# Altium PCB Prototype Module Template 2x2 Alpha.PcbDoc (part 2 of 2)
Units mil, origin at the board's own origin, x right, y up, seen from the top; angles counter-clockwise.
Board outline 1561.03 x 1620.2 mil, 6 copper layers (Component Side, Ground Plane (GND), Inner Layer 1, Inner Layer 2, Power Plane (VCC), Solder Side), stack 51.068 mil thick; 166 components, 80 nets, 785 pads, 445 vias.
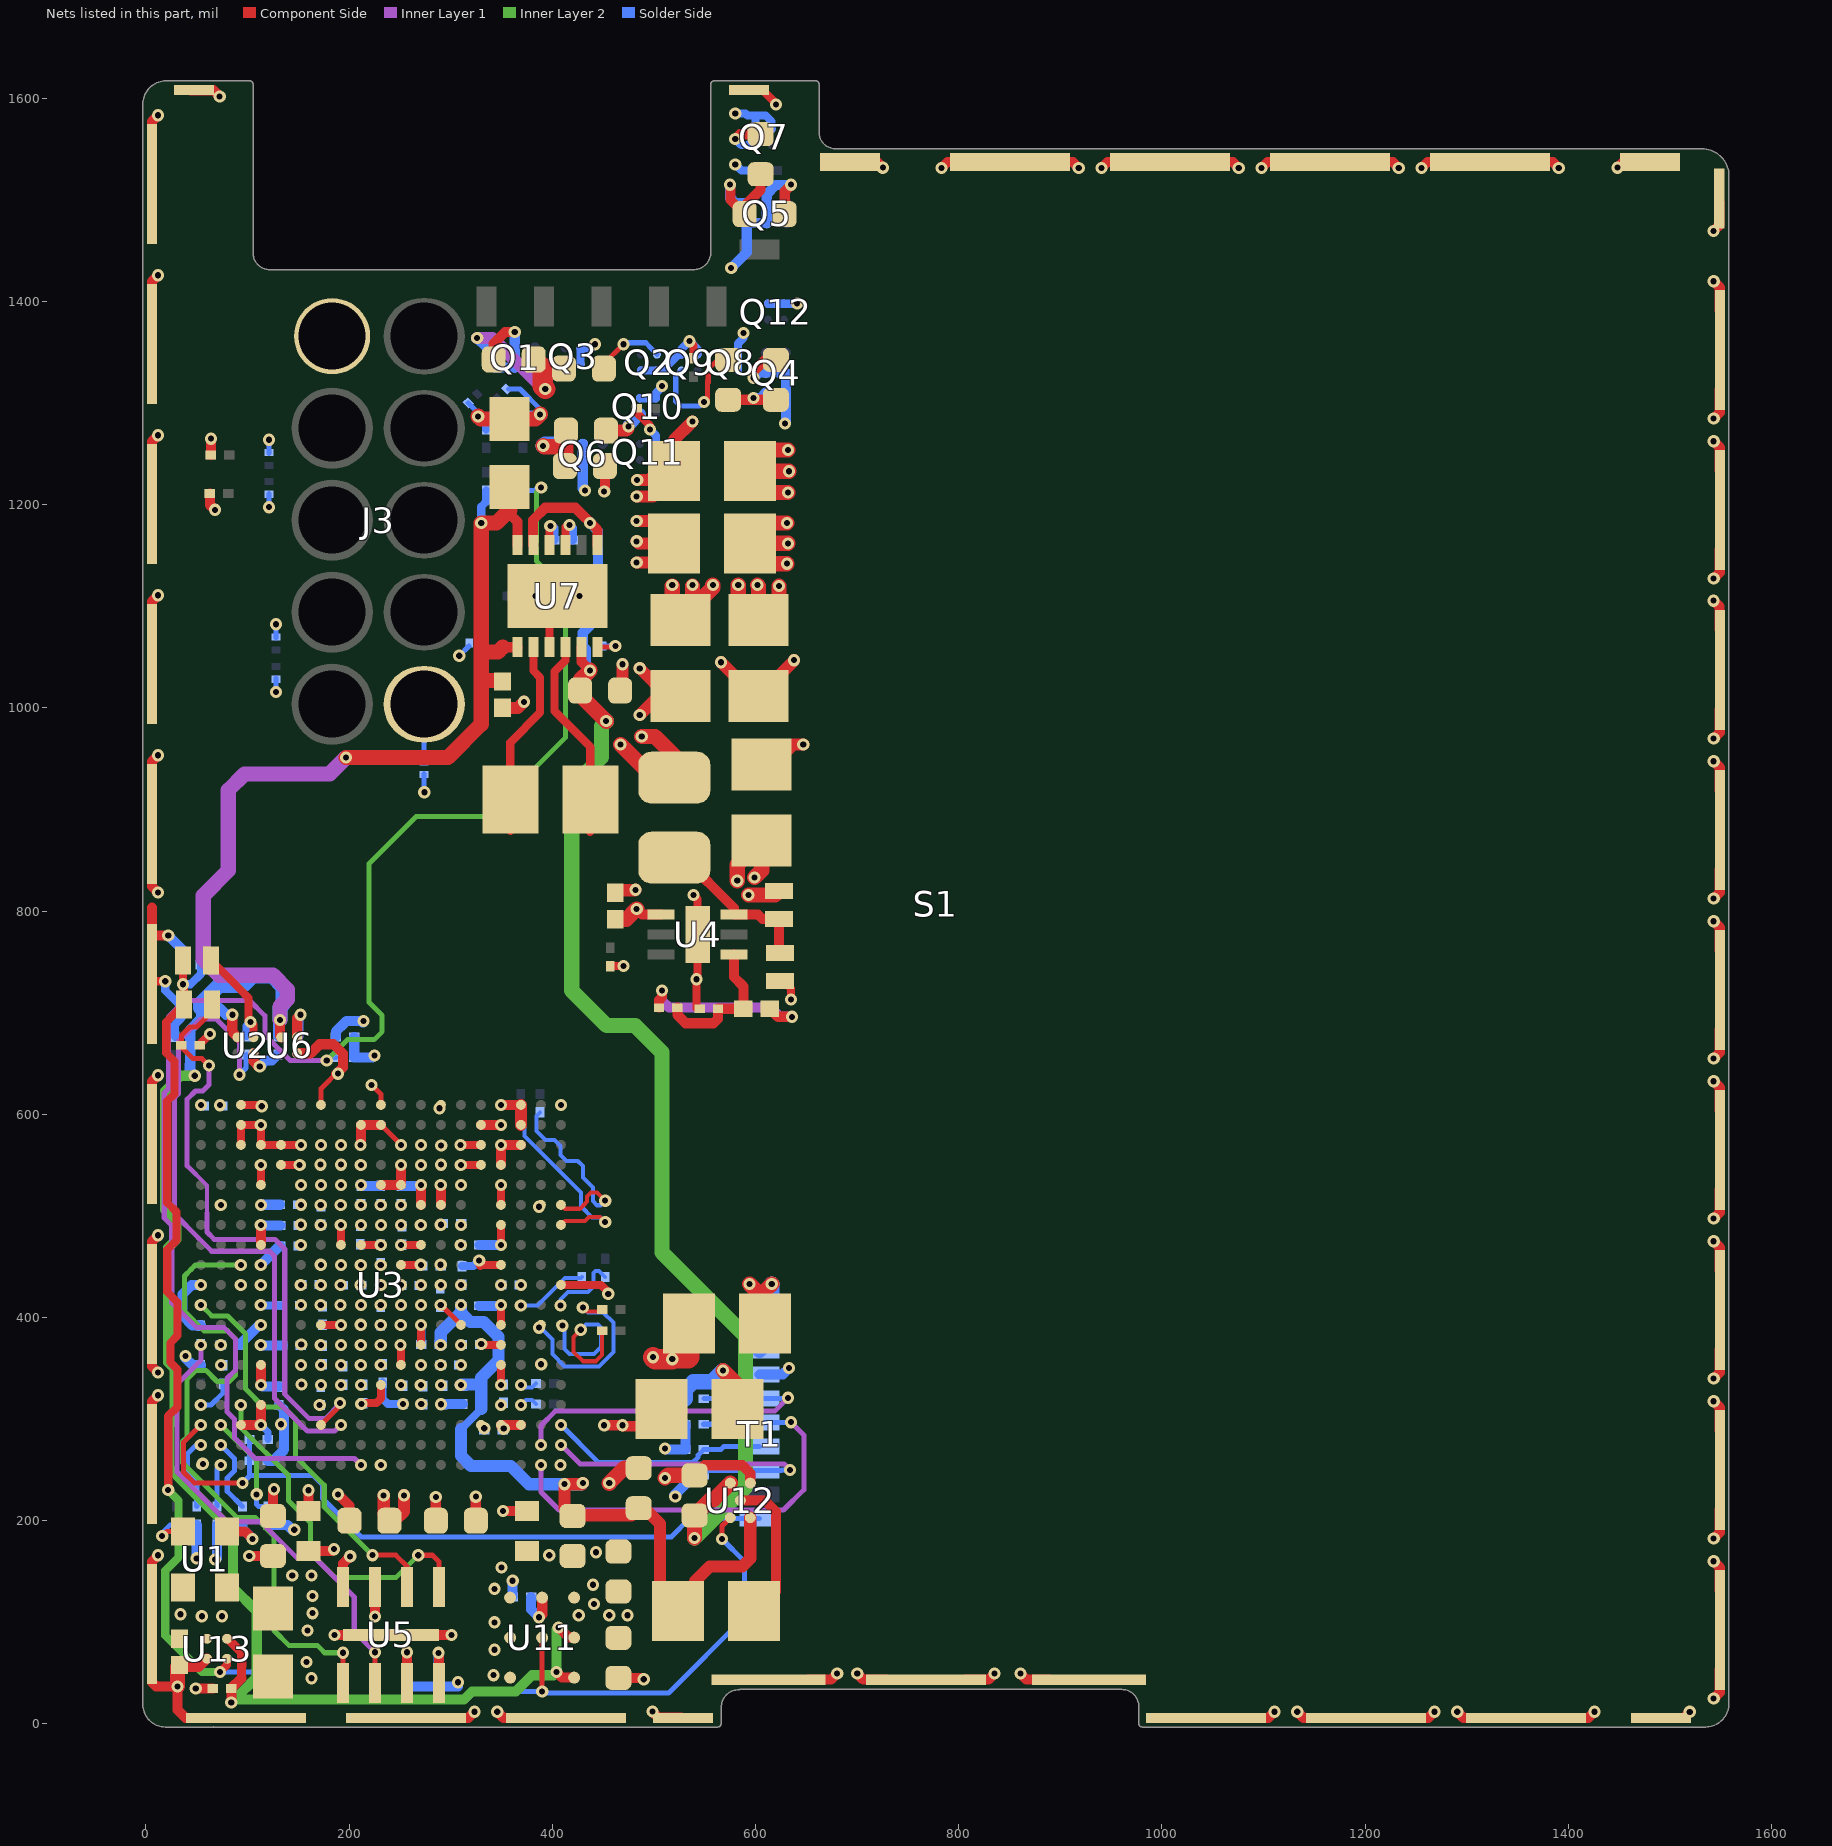
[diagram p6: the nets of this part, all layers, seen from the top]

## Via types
v1: diameter 12, hole 6, Component Side to Solder Side, tented both sides, 444 vias
v2: diameter 12, hole 6, Component Side to Solder Side, 1 vias

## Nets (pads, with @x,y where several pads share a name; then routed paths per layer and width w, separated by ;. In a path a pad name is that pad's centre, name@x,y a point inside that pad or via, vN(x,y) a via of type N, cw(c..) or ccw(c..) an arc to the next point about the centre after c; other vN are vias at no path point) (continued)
GND: C1.1 C2.1 C3.1 C4.1 C5.1 C6.1 C7.1 C8.1 C9.1 C11.1 C12.2 C13.2 C14.2 C15.2 C16.1 C17.2 C18.1 C19.1 C20.1 C21.1 C22.1 C23.1 C24.1 C25.1 C26.1 C27.1 C28.1 C29.1 C30.1 C31.1 C32.1 C33.1 C34.1 C35.1 C36.1 C37.1 C38.1 C39.1 C40.1 C41.1 C44.1 C49.1 C50.1 C51.1 C52.1 C53.1 C57.1 C58.1 C59.1 C60.1 C61.1 C62.1 C63.1 C64.1 C65.1 C66.1 C67.1 C68.1 C69.1 C70.1 C71.1 C72.1 C73.1 C77.1 C78.1 C81.1 C82.1 C94.1 C95.1 D2.1 J3.10 Q2.2 Q2.3 Q3.2 Q3.3 Q7.2 Q7.3 Q8.2 Q8.3 Q9.2 Q9.3 Q10.2 Q10.3 Q11.2 Q11.3 Q12.2 Q12.3 R1.2 R2.1 R5.2 R6.2 R9.2 R14.2 R15.2 R20.1 R21.2 R23.2 R24.2 R25.2 R30.2 R31.2 R32.2 R33.2 R41.1 R43.1 R45.1 R59.2 R60.2 R61.2 R62.2 S1.S T1.1 TVS1.2 TVS2.2 TVS3.2 TVS4.2 TVS5.2 TVS6.2 TVS7.2 TVS8.2 TVS9.2 U1.2 U2.B1 U3.A1 U3.A10 U3.A19 U3.C3 U3.C4 U3.C16 U3.C17 U3.D16 U3.E4 U3.E10 U3.E12 U3.E16 U3.F2 U3.F4 U3.F6 U3.F9 U3.F11 U3.F13 U3.F16 U3.F18 U3.G4 U3.G8 U3.G9 U3.G11 U3.G12 U3.G16 U3.H4 U3.H6 U3.H8 U3.H10 U3.H12 U3.H13 U3.H16 U3.J4 U3.J7 U3.J9 U3.J11 U3.J16 U3.K1 U3.K4 U3.K8 U3.K10 U3.K12 U3.K13 U3.K16 U3.K19 U3.L4 U3.L8 U3.L9 U3.L11 U3.L12 U3.L13 U3.L16 U3.M4 U3.M8 U3.M9 U3.M10 U3.M11 U3.M12 U3.M16 U3.N4 U3.N7 U3.N8 U3.N12 U3.N16 U3.P2 U3.P4 U3.P7 U3.P8 U3.P12 U3.P13 U3.P16 U3.P18 U3.R4 U3.R6 U3.R7 U3.R8 U3.R9 U3.R10 U3.R11 U3.R12 U3.R13 U3.R14 U3.R16 U3.T4 U3.T5 U3.T6 U3.T7 U3.T8 U3.T9 U3.T11 U3.T12 U3.T13 U3.T14 U3.T15 U3.T16 U3.U3 U3.U4 U3.U5 U3.U6 U3.U7 U3.U8 U3.U9 U3.U11 U3.U12 U3.U13 U3.U14 U3.U15 U3.U16 U3.U17 U3.V3 U3.V4 U3.V5 U3.V10 U3.V11 U3.V16 U3.V17 U3.W1 U3.W3 U3.W4 U3.W7 U3.W10 U3.W13 U3.W16 U3.W17 U3.W19 U4.7 U5.4 U5.9 U6.B1 U7.3 U7.9 U7.13 U11.C1 U11.C2 U11.C3 U12.A3 U13.B1 | length 6087
  Component Side w5: U3.W13@172.2,609.33 172.2,625.2 172.5,625.5 172.59,625.5 180.5,633.41 180.5,633.5 187,640 v1(189,640) ; v1(222,629) 231.26,619.74 U3.W10@231.26,609.33 ; U3.V10@231.26,589.65 v1(250.94,569.96) ; U3.J7@290.39,412.4 U3.H6@310,392.8
  Component Side w7: U3.F18@73.78,353.43 v1(74,353.2)
  Component Side w8: S1.S@8.56,731 v1(19,731) ; R41.1@53.06,668 53.06,669.06 v1(63,679) ; U3.U17@93.46,569.96 U3.V17@93.46,589.65 U3.V16@113.15,589.65 U3.U16@113.15,569.96 U3.U15@132.83,569.96 v1(152.52,569.96) ; U3.W17@93.46,609.33 U3.W16@113.15,609.33 114,608.48 v1(114,608) ; U3.R16@113.15,530.59 U3.T16@113.15,550.28 ; U3.T15@132.83,550.28 U3.T14@152.52,550.28 ; U3.H13@172.2,392.8 191.79,392.8 v1(191.87,392.72) ; v1(191.81,491.22) 191.89,491.15 U3.M12@191.89,471.54 ; U3.M11@211.57,471.54 231.07,471.54 v1(231.17,471.44) ; v1(212,314.94) 213.06,316 227,316 231.26,320.26 U3.E10@231.26,333.74 ; v1(250.69,373.03) 250.94,372.77 U3.F9@250.94,353.43 ; U3.L9@250.94,451.85 270.5,451.85 v1(270.55,451.9) ; v1(250.94,471.54) U3.M8@270.63,471.54 ; U3.G8@270.63,373.11 v1(270.63,392.8) ; v1(290.13,412.4) U3.J7@290.39,412.4 ; U3.T6@310,550.28 U3.T5@329.69,550.28 ; U3.U6@310,569.96 U3.U5@329.69,569.96 ; v1@328,453 v1(328,456) ; v1@329,451 329.85,451.85 U3.L4@349.37,451.85 ; v1(330,374) 330.89,373.11 U3.G4@349.37,373.11 ; v1(349.37,333.74) U3.F4@349.37,353.43 ; U3.H4@349.37,392.8 v1(349.37,412.48) ; v1(349.37,471.54) U3.N4@349.37,491.22 ; U3.P4@349.37,510.91 v1(349.37,530.59) ; U7.3@397.13,1059.8 397.13,1102.13 U7.13@405,1110 ; U3.K1@408.43,432.17 447.83,432.17 455,425 v1(455,423.33) ; U7.9@412.87,1160.2 413,1160.32 413,1178 415,1180 v1(417,1180) ; R9.2@457,745.94 469.94,745.94 v1(470,746) ; R61.2@482.94,1295 482.94,1290.93 492.21,1281.67 492.33,1281.67 496.02,1277.98 v1(496.02,1274.02) ; v1(535,1361) 539,1357 R62.2@539,1344.06 ; v1(539,816) 543,812 U4.7@543,777 543,735 v1@542,734 ; R14.2@541.94,704 541.94,733.94 v1@542,734 ; v1(542,733) v1@542,734 ; S1.S@595.47,1607.28 607.72,1607.28 620,1595 v1(620,1594) ; D2.1@624,731.22 627.78,731.22 635,724 v1(635,713)
  Component Side w10: 5.91,803.53 5.91,776.09 6,776 v1(22,776) ; S1.S@5.91,858.39 S1.S@5.91,885.83 ; S1.S@6,295 6,317.48 v1(12,323.48) ; S1.S@6,374.29 6,351.81 v1(12,345.81) ; S1.S@6,452.48 6,474.96 v1(12,480.96) ; S1.S@6,609.96 6,632.44 v1(12,638.44) ; S1.S@6,846.73 6,824.25 v1(12,818.25) ; S1.S@6,924.92 6,947.4 v1(12,953.4) ; S1.S@6,1082.4 6,1104.88 v1(12,1110.88) ; S1.S@6,1239.88 6,1262.36 v1(12,1268.36) ; S1.S@6,1397.36 6,1419.84 v1(12,1425.84) ; S1.S@6,1554.84 6,1577.32 v1(12,1583.32) ; v1(12,166) 5.91,159.91 S1.S@5.91,98.43 5.91,41.09 10,37 v1(31,37) 31,14 39,6 S1.S@45,6 ; C57.1@31,56.01 52.01,56.01 U13.B1@60.16,64.16 ; S1.S@44.09,1607.91 66.57,1607.91 v1(72.57,1601.91) ; v1(49,35) C94.1@65.94,35 ; R15.2@62.89,1211 62.89,1200.05 v1(67.94,1195) ; R31.2@63.89,1249 63.89,1264.94 v1(63.94,1265) ; U1.2@79.65,189.56 97.44,189.56 v1(105,182) ; U3.C17@93.46,294.37 U3.C16@113.15,294.37 U3.D16@113.15,314.06 ; v1(101.69,165.32) C60.1@125,165.32 ; U2.B1@105.87,660.13 105.87,652.13 111,647 v1(112,647) ; v1(113.15,333.74) U3.F16@113.15,353.43 ; U3.M16@113.15,471.54 U3.N16@113.15,491.22 ; U6.B1@148.87,660.13 162.13,660.13 171.04,669.04 184.63,669.04 194,659.67 194,646.41 v1@187.29,639.71 ; C16.1@160,170.32 v1@183.32,170.32 ; v1(185.6,87.6) U5.9@241.14,87.6 v1(300.6,87.6) ; v1(189,226) 200.32,214.68 C61.1@200.32,200 ; U5.4@193.9,134.84 193.9,157.9 v1(201,165) ; U3.U11@211.57,569.96 U3.V11@211.57,589.65 U3.V10@231.26,589.65 ; U3.R10@231.26,530.59 U3.R9@250.94,530.59 v1(250.94,550.28) ; v1(270.59,530.47) 270.63,530.43 U3.P8@270.63,510.91 ; v1(290.17,530.44) 290.32,530.29 U3.P7@290.32,510.91 ; S1.S@295,6 317.48,6 v1(323.48,12) ; C72.1@324.69,200 v1(324.69,223.68) ; U3.V5@329.69,589.65 v1(349.37,589.65) ; v1(345.81,12) 351.81,6 S1.S@374.29,6 ; U3.T4@349.37,550.28 v1(349.37,569.96) U3.U3@369.06,569.96 ; v1(349.37,609.33) U3.W3@369.06,609.33 ; v1(352.2,290.6) 349.37,293.43 U3.C4@349.37,294.37 U3.C3@369.06,294.37 ; U3.F2@388.17,354 U3.F2@388.74,353.43 ; C41.1@465,45.32 488.69,45.32 v1(490,44) ; v1(498.44,12.09) 504.44,6.09 S1.S@526.92,6.09 ; C81.1@540,244.68 549.86,254.55 587.06,254.55 594.84,246.77 U12.A3@594.84,237.05 ; S1.S@651.85,43.6 674.33,43.6 v1(680.33,49.6) ; S1.S@696.78,1537.76 719.26,1537.76 v1(725.26,1531.76) ; v1(700.14,49.6) 706.14,43.6 S1.S@728.62,43.6 ; v1(783.02,1531.31) 789.02,1537.31 S1.S@811.5,1537.31 ; S1.S@806.81,43.6 829.29,43.6 v1(835.29,49.6) ; v1(860.65,49.6) 866.65,43.6 S1.S@889.13,43.6 ; S1.S@889.69,1537.31 912.17,1537.31 v1(918.17,1531.31) ; v1(940.5,1531.31) 946.5,1537.31 S1.S@968.98,1537.31 ; S1.S@1047.17,1537.31 1069.65,1537.31 v1(1075.65,1531.31) ; S1.S@1082.4,6 1104.88,6 v1(1110.88,12) ; v1(1097.98,1531.31) 1103.98,1537.31 S1.S@1126.46,1537.31 ; v1(1133.21,12) 1139.21,6 S1.S@1161.69,6 ; S1.S@1204.65,1537.31 1227.13,1537.31 v1(1233.13,1531.31) ; S1.S@1239.88,6 1262.36,6 v1(1268.36,12) ; v1(1255.46,1531.31) 1261.46,1537.31 S1.S@1283.94,1537.31 ; v1(1290.69,12) 1296.69,6 S1.S@1319.17,6 ; S1.S@1362.13,1537.31 1384.61,1537.31 v1(1390.61,1531.31) ; S1.S@1397.36,6 1419.84,6 v1(1425.84,12) ; v1(1448.36,1531.76) 1454.36,1537.76 S1.S@1476.84,1537.76 ; S1.S@1491.02,5.91 1513.5,5.91 v1(1519.5,11.91) ; v1(1542.91,1105.57) 1548.91,1099.57 S1.S@1548.91,1077.09 ; v1(1542.91,1469.43) 1548.91,1475.43 S1.S@1548.91,1497.91 ; v1(1543.04,24.95) 1549.04,30.95 S1.S@1549.04,53.43 ; v1(1543.04,160.09) 1549.04,154.09 S1.S@1549.04,131.61 ; v1(1543.04,182.43) 1549.04,188.43 S1.S@1549.04,210.91 ; v1(1543.04,317.57) 1549.04,311.57 S1.S@1549.04,289.09 ; v1(1543.04,339.91) 1549.04,345.91 S1.S@1549.04,368.39 ; v1(1543.04,475.06) 1549.04,469.06 S1.S@1549.04,446.57 ; v1(1543.04,497.39) 1549.04,503.39 S1.S@1549.04,525.87 ; v1(1543.04,632.54) 1549.04,626.54 S1.S@1549.04,604.06 ; v1(1543.04,654.87) 1549.04,660.87 S1.S@1549.04,683.35 ; v1(1543.04,790.02) 1549.04,784.02 S1.S@1549.04,761.54 ; v1(1543.04,812.35) 1549.04,818.35 S1.S@1549.04,840.83 ; v1(1543.04,947.5) 1549.04,941.5 S1.S@1549.04,919.02 ; v1(1543.04,969.83) 1549.04,975.83 S1.S@1549.04,998.31 ; v1(1543.04,1127.31) 1549.04,1133.31 S1.S@1549.04,1155.79 ; v1(1543.04,1262.46) 1549.04,1256.46 S1.S@1549.04,1233.98 ; v1(1543.04,1284.79) 1549.04,1290.79 S1.S@1549.04,1313.27 ; v1(1543.04,1419.94) 1549.04,1413.94 S1.S@1549.04,1391.46
  Component Side w12: C77.1@351,1000.01 366.01,1000.01 v1(372,1006) ; U3.V3@369.06,589.65 U3.W3@369.06,609.33 ; C9.1@462,817.99 464.51,820.5 481.5,820.5 v1(482,821) ; C50.1@466.69,1017 469,1019.32 v1(469,1043) ; v1(483,1143) 500.6,1143 C8.1@519.6,1162 ; v1(483,1164) 485,1162 C8.1@519.6,1162 ; v1(483,1184) 497.6,1184 C8.1@519.6,1162 ; v1(483,1208) 499,1208 519.6,1228.6 C11.1@519.6,1233 ; v1(483.52,1224.48) 495.48,1224.48 504,1233 C11.1@519.6,1233 ; v1(486,993) 504.6,1011.6 C31.1@513.4,1011.6 ; v1(486,1039) C31.1@513.4,1011.6 ; C31.1@526,1011.6 C31.1@513.4,1011.6 ; v1(538,1282) 519.6,1263.6 C11.1@519.6,1233 ; v1(566,1045) 599.4,1011.6 C53.1@603,1011.6 638,1046.6 v1(638,1047) ; C49.1@606,944.4 617.4,944.4 637,964 v1(647,964)
  Component Side w15: v1(31,37) 31,56.01 C57.1@33,58.01 ; v1(327,1287) 329.54,1284.46 C52.1@358,1284.46 383.46,1284.46 v1(388,1289) ; v1(456,237) 470.69,251.68 C82.1@485,251.68 ; v1(511,242) 514,245 514.32,244.68 C81.1@540,244.68 ; v1(568,348) 582.4,333.6 C38.1@582.4,310 C38.1@582.4,330.4 ; v1(594,433) C78.1@609.4,417.6 ; C78.1@609.4,394 C78.1@609.4,417.6 ; v1(616,433) 609.4,426.4 C78.1@609.4,417.6
  Solder Side w5: v1(121,1197.61) TVS8.2@121,1211.21 ; TVS7.2@121,1250.39 v1(121,1264) ; v1(128,1015.61) TVS6.2@128,1029.21 ; TVS5.2@128,1068.79 v1(128,1082.39) ; v1@273.86,917 TVS9.2@273.86,935.35 ; v1(308.38,1051.38) TVS2.2@318,1061 ; TVS4.2@317.19,1300.19 329,1288.37 v1@329,1287 ; TVS3.2@356.81,1313.81 368.19,1313.81 388,1294 v1(388,1289) ; TVS1.2@368.39,1110 v1(383.35,1110)
  Solder Side w7: v1(113.07,294.29) 120.06,287.31 C14.2@120.06,280
  Solder Side w8: v1(19,731) 19,721.94 C32.1@35.94,705 35,704.05 35,695 28.54,688.54 R59.2@28.54,676.38 ; v1(113.07,412.4) 113.47,412 C73.1@133.94,412 ; C5.1@173.69,392.71 v1(191.87,392.72) ; C1.1@211,471.94 211.5,471.44 v1(231.17,471.44) ; C36.1@233,335.94 233,320 238.06,314.94 v1(253,314.94) ; v1(270.63,392.8) 271.12,392.31 C64.1@271.12,373.52 ; C6.1@311.17,450.57 322.57,450.57 v1(328,456) ; v1@328,1288 v1(327,1287) 329,1287 335,1281 R5.2@335,1274.06 ; R6.2@371,1274.06 371,1281 379,1289 v1(388,1289) ; v1(417,1180) 420.06,1176.94 R43.1@420.06,1165 ; Q3.2@427.87,1338.13 Q3.3@427.87,1353.87 437.87,1353.87 v1(442,1358) ; Q10.3@486.13,1304.87 Q10.2@501.87,1304.87 501.87,1309.87 509,1317 v1(508,1317) ; Q2.2@487.13,1332.13 Q2.3@502.87,1332.13 508.69,1332.13 524.44,1347.87 Q9.3@527.13,1347.87 527.13,1353.13 v1(535,1361) 542.87,1353.13 Q9.2@542.87,1347.87 ; v1(496.02,1274.02) 501.87,1268.13 Q11.3@501.87,1259.87 Q11.2@501.87,1244.13 ; v1(580,1535) 586,1529 R60.2@602.94,1529 ; v1(580,1585) 590,1585 592,1583 602,1583 ; Q8.2@582.87,1332.13 Q8.3@582.87,1347.87 582.87,1358.87 588,1364 v1(588,1369) ; Q7.3@600.13,1569.87 600.13,1581.13 602,1583 ; Q12.3@612.13,1397.87 Q12.2@627.87,1397.87 640.87,1397.87 v1(641,1398) ; Q7.2@615.87,1569.87 615.87,1577.13 610,1583 602,1583
  Solder Side w10: v1(22,776) 35.94,762.06 R1.2@35.94,747 ; v1(50,163) R24.2@50,195.94 ; R20.1@54,392.06 45.94,392.06 36,402 36,423 45.09,432.09 v1(54.02,432.09) ; v1(68,162) 69,162 70,163 R25.2@70,195.94 ; R21.2@91.81,373.03 111.5,392.72 v1(113.07,392.72) ; R23.2@95,195.94 95,192 v1(105,182) ; v1(112,647) 118,653 124.06,653 C39.1@130,658.94 ; v1(113.07,373.03) 113.58,372.52 C18.1@134.12,372.52 ; v1(113.07,451.77) 131.82,470.52 C69.1@132.12,470.52 ; v1(113.07,491.14) 113.69,490.52 C28.1@132.12,490.52 ; v1(113.15,333.74) 114.83,332.06 C34.1@131,332.06 ; v1(113.15,510.91) 113.24,511 C71.1@131.94,511 ; C3.1@205.06,676 R2.1@205.06,656 223,656 v1(225,658) ; v1(211.57,530.59) 212.59,529.57 C30.1@231.17,529.57 ; C33.1@251.17,529.57 269.7,529.57 v1(270.59,530.47) ; C13.2@257,36.94 C12.2@288,36.94 306.94,36.94 307,37 v1(307,41) ; v1(290.32,314.63) 290.63,314.94 C63.1@312,314.94 ; C65.1@328.23,411.52 348.41,411.52 v1(349.37,412.48) ; C24.1@328.23,471.52 v1(349.37,471.54) ; R45.1@360.94,125 v1(360.94,140.94)
  Solder Side w15: R32.2@530.94,320 530.94,329.02 538.76,336.83 556.83,336.83 v1(568,348) ; T1.1@604,367.68 604,393 616,405 v1(616,433)
  other v1: 163,45 342,48 158,61 343,73 343,100 343,133 350,154 397,166 443,169 185,172 231.18,254.92 408,255 56,256 171,314 271,315 191.89,333.74 172.2,353.43 211.5,353.35 310,353.35 389,354 191.89,373.11 211.5,373.03 231.09,392.63 211.54,412.44 250.91,412.44 113.07,432.09 172.13,431.97 191.74,432.09 231.18,432.03 270.59,432.04 349.37,432.17 172.13,451.91 191.93,451.77 211.5,451.84 270.55,490.98 290.24,491.3 387,509 73.7,510.83 172.09,510.86 191.71,510.83 309.99,530.44 152.52,530.59 172.2,530.59 191.89,530.59 113.07,550.2 151.34,550.2 171.88,550.44 192.06,550.44 211.5,550.2 270.59,550.24 290.48,550.44 309.92,550.27 290.59,569.44 172.2,569.96 192.04,569.88 211.09,569.94 270.63,569.96 309.59,569.94 113.07,589.46 289,606 54.09,609.33 408.43,609.33 274,917 426.65,1110
INITN: R26.1 U3.C18 | length 104.7
  Inner Layer 2 w5: v1(73.7,294.29) 109,258.99 v1(109,226)
  Solder Side w5: v1(109,226) 109,216 110.94,214.06 R26.1@120,214.06
NetC10_1: C10.1 R13.2 R14.1 U4.1 | length 144.3
  Component Side w10: R13.2@523.06,705 523.06,697.94 531.33,689.67 558.67,689.67 563.06,694.06 R14.1@563.06,704 C10.1@588.01,704 588.01,725.99 578.83,735.17 U4.1@578.83,757.31
NetD1_1: D1.1 D2.2 L2.2 U4.3 | length 165.7
  Component Side w10: L2.2@520,852.63 529.37,852.63 578.83,803.17 U4.3@578.83,796.68 602.32,796.68 606.78,792.22 D1.1@623,792.22 623,759.78 D2.2@624,758.78
NetL1_1: L1.1 U12.B2 | length 154.2
  Component Side w10: U12.B2@585,220 609,220 620,209 620,130.6 L1.1@594.4,105
NetL6_1: L6.1 U7.2 | length 202.2
  Component Side w8: L6.1@359,879 358.63,879.37 L6.1@358.63,910 358.63,966 388,995.37 388,1030 381.38,1036.62 ; 381.38,1043 381.38,1036.62 ; U7.2@381.38,1059.8 381.38,1036.62
NetL6_2: L6.2 U7.4 | length 201.1
  Component Side w8: U7.4@412.87,1059.8 412.87,1046.87 402,1036 402,997 437.37,961.63 L6.2@437.37,910 437.37,878.37 L6.2@437,878
NetQ1_1: Q1.1 R11.2 R12.1 | length 163.1
  Component Side w20: R11.2@381.69,1343 R11.2@390.69,1334 ; v1(393,1314) 390.69,1316.31 R11.2@390.69,1334 ; R12.1@411.32,1334 R11.2@390.69,1334
  Inner Layer 1 w12: v1(326,1364) 341,1364 391,1314 v1(393,1314)
  Solder Side w10: v1(326,1364) 335.16,1354.84 Q1.1@343.32,1354.84
NetQ2_4: Q2.4 R12.2 | length 99.2
  Component Side w5: R12.2@450.69,1334 450.69,1338.69 v1(470,1358)
  Solder Side w5: v1(470,1358) v1@471.41,1359.41 ; 497.66,1353.66 491.9,1359.41 ; Q2.4@502.87,1347.87 502.87,1348.44 491.9,1359.41 ; v1@471.41,1359.41 491.9,1359.41 ; v1@471.41,1359.41 484,1359.41 491.9,1359.41
NetQ4_1: Q4.1 R44.2 R58.1 | length 63.7
  Component Side w10: R58.1@573,1303.32 v1@596.32,1303.32 ; v1(598,1305) v1@596.32,1303.32 ; R44.2@620,1303.31 v1@596.32,1303.31
  Solder Side w10: v1(598,1305) 604.84,1305 Q4.1@610.16,1310.32
NetQ5_1: Q5.1 R16.2 R18.1 | length 112.2
  Component Side w10: v1(575,1515) 575.31,1514.69 575.31,1500 R16.2@589.31,1486 589.31,1494.31 605,1510 R18.1@605,1525.32
  Solder Side w10: v1(575,1515) 575,1502 580.16,1496.84 Q5.1@591.32,1496.84
NetQ6_1: Q6.1 R17.2 R19.1 | length 78.2
  Component Side w15: v1(391,1258) 392,1257 413.32,1257 ; R17.2@412.31,1238 413.32,1239 413.32,1257 ; R19.1@413.32,1273 413.32,1257
  Solder Side w15: v1(391,1258) 392.84,1259.84 Q6.1@410.32,1259.84
NetQ7_4: Q7.4 R18.2 | length 49.5
  Component Side w10: v1(580,1560) 584.69,1564.69 R18.2@605,1564.69
  Solder Side w8: v1(580,1560) 585.87,1554.13 Q7.4@600.13,1554.13
NetQ9_4: Q9.4 R58.2 | length 126.7
  Component Side w5: v1(549.2,1301.16) 549,1300.96 549,1300 552.7,1303.7 552.7,1322.28 553.42,1323 ; 553.42,1320.42 553.42,1323 ; R58.2@573,1342.69 562.69,1342.69 553.42,1333.42 553.42,1323
  Solder Side w5: Q9.4@527.13,1332.13 521.5,1326.5 521.5,1301.5 526,1297 545.04,1297 v1(549.2,1301.16)
NetQ10_4: Q10.4 R19.2 | length 41.9
  Component Side w12: R19.2@452.69,1273 473,1273 475,1275 v1(475,1277)
  Solder Side w12: v1(475,1277) 475,1278 Q10.4@486.13,1289.13
NetR21_1: R21.1 U3.G18
  other v1: 73.7,373.03
NetR23_1: R23.1 U3.B18 | length 78.5
  Solder Side w5: v1(73.7,274.61) 87.2,261.11 87.2,249.16 ; 85.44,247.4 87.2,249.16 ; R23.1@94.5,214.55 R23.1@95,214.06 80,229.06 80,241.96 87.2,249.16
NetR24_1: R24.1 U3.B19 | length 72.3
  Solder Side w5: R24.1@50,214.06 50,237 41,246 41,266 49.61,274.61 v1(54.02,274.61)
NetR25_1: R25.1 U3.A18 | length 42.4
  Solder Side w5: R25.1@70,214.06 70,251.22 v1(73.7,254.92)
NetR30_1: R30.1 U3.D19 | length 35.9
  Solder Side w5: v1(54.02,313.98) 63.98,313.98 76,326 R30.1@76,334.94
NetR33_1: R33.1 U3.W18
  other v1: 73,609
NetR35_1: R35.1 U6.B2 | length 42.4
  Component Side w10: U6.B2@148.87,675.87 148.87,694.87 v1(152,698)
  Solder Side w10: R35.1@150,677.06 v1@150,696
NetR39_2: R39.2 U7.6 | length 32.3
  Component Side w5: U7.6@444.5,1059.67 U7.6@444.37,1059.8 460.8,1059.8 v1(462,1061)
  Solder Side w5: R39.2@448.06,1061 v1(462,1061)
NetR43_2: R43.2 U7.10 | length 38.8
  Component Side w8: U7.10@397.13,1160.2 397.13,1176.13 400,1179 v1(398,1179)
  Solder Side w8: v1(398,1179) 400,1179 401.94,1177.06 R43.2@401.94,1165
NetR45_2: R45.2 U11.B1 | length 43.9
  Component Side w10: v1(387,105) 390,108 U11.B1@390,124.37
  Solder Side w10: R45.2@379.06,125 379.06,112.94 v1(387,105)
NetR52_1: R52.1 U1.3 | length 44.6
  Component Side w5: v1(16,185) 18.56,187.56 20.56,189.56 U1.3@36.35,189.56
  Solder Side w5: v1@16,187.12 v1(16,185) 16,188 23.94,195.94 R52.1@30,195.94
POWER_EN: D3.2 D4.2 R1.1 U11.B2 U12.C1 U13.B2 | length 1548.5
  Component Side w5: v1(390,32) U11.B2@390,85 ; v1(567,182) 567,194.8 U12.C1@575.16,202.95
  Component Side w8: v1(21.91,230.17) 21.91,302.91 31,312 31,348.79 24,355.79 24,375.21 31,382.21 31,415 21,425 21,467 30,476 30,504 21,513 21,613 28,620 28,652.21 20,660.21 20,690.78 D4.2@37.22,708 37.22,727.22 v1(36.42,728.02) D3.2@36.42,751.61 ; v1(73,51) 79.84,57.84 U13.B2@79.84,64.16
  Inner Layer 2 w8: v1(21.91,230.17) 32,220.08 32,163.79 21.21,153 21,153 19,151 19,87 55,51 v1(73,51)
  Solder Side w5: v1(73,51) 109,51 136.56,23.44 315.44,23.44 324,32 v1(390,32) ; v1@391.5,30.5 514.5,30.5 589,105 589,160 v1(567,182)
  Solder Side w8: v1(36.42,728.02) 44,728.02 54.06,738.08 R1.1@54.06,747
POWER_HOLD: D4.1 R41.2 U3.C13 | length 605.2
  Component Side w5: v1(62.02,648.02) 55.04,655 46,655 34.94,666.05 R41.2@34.94,668 34.94,677.94 43,686 50,686 64.78,700.78 D4.1@64.78,708 ; U3.C13@172.2,294.37 191,313.17 v1(191,316)
  Inner Layer 1 w4: 48.92,541.08 60,530 60,503
  Inner Layer 1 w5: 48.92,541.08 40.59,549.41 40.59,614.92 48.67,623 56,623 62,629 v1(62.02,648.02) ; 60,503 60,484.14 67.14,477 127,477 136.65,467.35 136.65,324.58 160.73,300.5 171,300.5 176.59,300.5 191,314.91 v1(191,316)
PROGRAM_N: C14.1 R22.2 T1.7 U3.C19 | length 745.5
  Component Side w5: U3.C19@54.09,294.37 v1(54.02,294.29) 37,277.28 37,248 48,237 82,237 ; v1@91,237 82,237 ; v1(95,237) 82,237
  Solder Side w5: v1(95,237) 101.94,243.94 R22.2@101.94,259 C14.1@101.94,280 ; 102.39,244.5 125,244.5 ; 137.5,244.5 125,244.5 ; 165.59,243.5 170.09,239 ; 580,202.32 T1.7@604,202.32 ; T1.7@593.74,202.32 535.32,202.32 517,184 211.91,184 174,221.91 174,235.09 170.09,239 ; 125,244.5 164.59,244.5 170.09,239
RX_CLK_N: C90.2 U3.J1 | length 71.9
  Solder Side w4: v1(408,412) 408,417.66 415.34,425 435,425 440.33,430.33 440.33,444 442.27,445.94 446.01,445.94 C90.2@452,439.94
RX_CLK_P: C89.2 U3.J3 | length 71.6
  Solder Side w4: v1(369,412) 385.37,412 412.37,439 428.05,439 C89.2@429,439.94
RX_N: C88.2 U3.P1 | length 203.6
  Component Side w4: U3.P1@408.43,510.91 412.27,507.06 427,507.06 430.94,511 431,511 434,514 434,519 438,523 444,523 447,520 v1(452,515)
  Solder Side w4: 384.5,596.44 384.5,590 ; C88.2@388,601.94 384.5,598.44 384.5,590 ; v1(452,515) 447.5,510.5 444,510.5 440,514.5 440,528 430,538 430,549 425,554 414,554 408,560 408,569 402.31,574.69 393.31,574.69 384.5,583.5 384.5,590
RX_P: C87.2 U3.N1 | length 203.6
  Component Side w4: U3.N1@408.43,491.22 412.27,495.06 431.97,495.06 435.91,499 447,499 v1(452,494)
  Solder Side w4: C87.2@369,601.94 372.5,598.44 372.5,589 ; 372.5,596.44 372.5,589 ; v1(452,494) 447.5,498.5 439.03,498.5 428,509.53 428,523 372.5,578.5 372.5,587.5 372.5,589
SPI_FLASH_CLK: R20.2 U3.G19 U5.6 | length 459.3
  Component Side w5: U5.6@225.39,40.35 v1(225.39,70.61)
  Inner Layer 1 w5: 48.16,352.06 54.02,357.92 v1(54.02,373.03) ; 52.5,356.41 46,349.91 30.52,334.42 30.52,323.71 30.52,248.25 79.77,199 113,199 149,163 167,163 205,125 205,91 v1(225.39,70.61)
SPI_FLASH_CS_N: U3.D17 U5.1 | length 347.3
  Component Side w5: v1(268,166) 282,166 288.39,159.61 U5.1@288.39,134.84
  Inner Layer 2 w5: v1(93.39,313.98) 93.39,291.61 140.27,244.73 140.27,219.73 162,198 162,168 186,144 246,144 v1(268,166)
SPI_FLASH_MISO: U3.J19 U5.2 | length 410.1
  Component Side w5: v1(222.89,166.11) 246,166.11 256.89,155.22 U5.2@256.89,134.84
  Inner Layer 2 w5: v1(54.02,412.4) 64.71,401.71 80.29,401.71 98,384 98,329.8 115.8,312 135.09,312 147,300.09 147,263.5 ; 147,278 147,263.5 ; v1(222.89,166.11) 175.5,213.5 175.5,231.59 175.5,235 147,263.5
SPI_FLASH_MOSI: U3.L17 U5.5 | length 654
  Component Side w5: U5.5@193.9,40.35 v1(193.9,70.1)
  Inner Layer 2 w5: v1(93.39,451.77) 48.86,451.77 44.59,447.5 44.5,447.5 38,441 38,406 57,387 80,387 88,379 88,343 82,337 70,337 59,348 49.26,348 40.59,339.33 40.59,329.59 40.52,329.52 40.52,288.62 40.59,288.54 40.59,282.59 36,278 36,257 42.5,250.5 42.5,250.41 50.41,242.5 50.5,242.5 90,203 108,203 126,185 126,92 141,77 169,77 175,71 175.9,70.1 v1(193.9,70.1)
TCK: R32.1 T1.3 U3.B2 | length 374.1
  Inner Layer 1 w5: v1(388.74,274.68) 388.74,293.78 402.83,307.87 618.87,307.87 v1(632,321)
  Solder Side w5: R32.1@549.49,320.43 T1.3@593.74,320.43 ; 576,320.43 T1.3@604,320.43 631.43,320.43 v1(632,321)
TDI: R28.2 T1.5 U3.C1 | length 233.2
  Solder Side w5: v1(408.43,294.37) 445.3,257.5 538.5,257.5 543.56,262.56 543.56,264.51 R28.2@549.06,270 565.81,270 569,273.19 579,273.19 ; T1.5@593.74,273.19 579,273.19 ; T1.5@604,273.19 579,273.19
TDO: R29.2 T1.6 U3.B1 | length 323
  Inner Layer 1 w5: v1(408.43,274.68) 427.11,256 628,256 v1(634,250)
  Solder Side w5: R29.2@549.06,245 553.62,249.57 625.57,249.57 625.57,249.43 626.13,250 v1(634,250)
TMS: R27.2 T1.4 U3.A2 | length 475.2
  Inner Layer 1 w5: v1(388.74,255) 388.74,228.26 406.5,210.5 511,210.5 ; 526.59,210.5 511,210.5 ; v1(635,297) 647.5,284.5 647.5,230.5 627.5,210.5 511,210.5
  Solder Side w5: R27.2@549.06,295 571.19,295 573,296.81 T1.4@604,296.81 634.81,296.81 v1(635,297)
TX_CLK_N: C86.2 U3.H2 | length 191.6
  Component Side w4: v1(430,410) 434,406 443,406 ; C86.2@444.95,406 443,406 ; C86.2@448.94,408 446.95,406 443,406
  Solder Side w4: v1(387,390) 388.38,390 400,378.38 400,364 412,352 446,352 460,366 460,395 450,405 436,405 435,405 v1(430,410)
TX_CLK_P: C85.2 U3.H1 | length 190.3
  Component Side w4: v1(428,388) 421,381 421,366 430,357 443,357 448.94,362.94 C85.2@448.94,387
  Solder Side w4: v1(410,392) 412,390 412,368.97 416.97,364 441.03,364 448,370.97 448,390.03 445.03,393 433,393 v1(428,388)
TX_N: C84.2 U3.E3 | length 17.7
  Solder Side w4: v1(369.06,333.74) 371.8,331 379.94,331 C84.2@383.94,335
TX_P: C83.2 U3.D3 | length 18.6
  Solder Side w4: v1(369.06,314.06) 374,319 379.95,319 C83.2@383.94,315
V1P2: C1.2 C2.2 C18.2 C19.2 C20.2 C21.2 C22.2 C23.2 C24.2 C25.2 C27.2 C28.2 C29.2 C30.2 C33.2 C40.2 C41.2 C78.2 U3.E8 U3.E14 U3.F7 U3.G6 U3.G10 U3.G14 U3.H9 U3.H11 U3.J8 U3.J10 U3.J12 U3.K9 U3.K11 U3.L10 U3.M6 U3.N9 U3.N10 U3.N11 U3.N14 U3.P9 U3.P10 U3.P11 U11.A1 | length 71.1
  Component Side w10: U3.E14@152.52,333.74 152.74,333.74 v1(153,334)
  Component Side w20: v1(499,361) 501,359 v1(518,359) 519,360 534,360 534.6,360.6 C78.2@534.6,394
  other v1: 426,107 456,107 474,107 441,118 440,137 270.55,333.48 290.19,353.35 152.89,373.49 231.09,372.94 310,373.03 211.5,392.84 250.82,392.72 191.63,412.4 231.14,412.44 270.59,412.44 211.24,432.09 250.95,432.09 231.09,451.86 309.91,471.44 152.44,491.29 211.57,491.22 231.26,491.22 250.94,491.22 211.5,510.84 231.09,510.91 250.98,510.83
V2P5: C59.2 C63.2 C64.2 C65.2 C82.2 L1.2 U3.E6 U3.G7 U3.J6 U12.C3 | length 771
  Component Side w12: C59.2@420,204.69 412,212.69 v1(412,236) 429,236 v1(430,237) ; C59.2@420.67,205.35 478.04,205.35 C82.2@485,212.31 490.69,212.31 506,197 506,118.6 519.6,105 540.5,125.9 540.5,140.5 555,155 566,155 587,155 594.84,162.84 U12.C3@594.84,202.95
  Solder Side w8: 310,290 330,310
  Solder Side w12: v1(290.19,373.03) 290.19,385.18 310.06,405.06 ; v1(309.92,333.61) 310.31,334 330,334 ; 310,290 310,264 320,254 359,254 377,236 v1(412,236) v1@429,236 ; v1(310.06,412.4) 310.06,405.06 ; 330,310 330,334 ; 310.06,405.06 312.11,403 312.11,402.63 319.22,395.52 332.52,395.52 347,381.04 347,358 330,341 330,334
V3P3: C3.2 C4.2 C5.2 C6.2 C7.2 C9.2 C12.1 C13.1 C15.1 C16.2 C17.1 C26.2 C34.2 C35.2 C36.2 C37.2 C38.2 C44.2 C51.2 C57.2 C58.2 C60.2 C61.2 C62.2 C66.2 C67.2 C68.2 C69.2 C70.2 C71.2 C72.2 C73.2 C95.2 L2.1 R22.1 R26.2 R27.1 R28.1 R29.1 R34.2 T1.2 U1.1 U1.4 U3.C5 U3.C15 U3.D4 U3.E7 U3.E9 U3.E11 U3.E13 U3.F8 U3.F10 U3.F12 U3.F14 U3.G13 U3.J13 U3.J14 U3.K3 U3.K6 U3.K7 U3.K14 U3.K17 U3.L7 U3.M14 U3.N6 U3.N13 U3.P14 U4.4 U5.3 U5.7 U5.8 U13.A1 | length 788.9
  Component Side w10: C60.2@125,204.69 125,231 v1(126,231) ; U3.C15@132.83,294.37 132.83,294.83 v1(133,295) ; C16.2@160,209.68 v1(160,230) ; v1(225.39,105.61) U5.3@225.39,134.84 ; U5.7@256.89,40.35 v1(256.89,70.58) ; C72.2@285.31,200 v1(285.31,223.31) ; v1(288,70) 288.39,69.61 U5.8@288.39,40.35 ; v1(351.32,209.68) C37.2@375,209.68 ; v1(451,294) v1(469,294) 469,293 490.6,293 C38.2@507.6,310 ; v1(483,802) 488.32,796.68 U4.4@507.17,796.68
  Component Side w12: v1(234,225) 234,205.69 C61.2@239.69,200 245,200 254,209 v1(254,225)
  Component Side w15: C9.2@462,792.01 473.01,792.01 v1(483,802) ; v1(467,964) 499.63,931.37 L2.1@520,931.37 520,953 501,972 v1(488,972)
  Solder Side w10: v1(39,362) 39,360 45.94,353.06 R34.2@54,353.06 ; R26.2@120,195.94 139.06,195.94 143.84,191.16 v1(146,191.16) ; R22.1@120.06,259 125,259 136,270 136,308.94 C34.2@131,313.94 ; C3.2@186.94,676 186.94,681.48 ; 195.23,689.77 186.94,681.48 ; v1@213.34,690.33 214,690.33 v1(214,692) 197.46,692 186.94,681.48 ; v1(256.89,70.58) 257,70.47 C13.1@257,55.06 ; C12.1@288,55.06 v1(288,70) ; v1(511,271) 512,270 R28.1@530.94,270 R27.1@530.94,295 ; v1(521,224) 520,225 530.94,235.94 R29.1@530.94,245 ; T1.2@604,344.06 626.8,344.06 v1(633,350.25)
  other v1: 159,92 55,106 75,106 34,108 164,109 164,126 144,146 163,146 333,291 349.37,314.06 172.2,333.74 211.57,333.74 250.94,333.74 290.32,333.74 152.52,353.43 191.89,353.43 231.18,353.35 270.63,353.43 172.13,372.97 152.48,412.44 172.09,412.43 93.39,432.09 152.45,432.09 290.24,432.08 310.07,431.94 369.06,432.17 290.09,451.91 152.46,471.44 172.13,490.97 310.09,490.97 152.56,510.94
V3P3_ALWAYS: C32.2 C39.2 C52.2 C77.2 C94.2 R3.2 U2.A2 U6.A2 U7.1 U7.12 U11.A2 U11.A3 U13.A2 | length 2532.4
  Component Side w9: U13.A2@79.84,83.84 80.55,83.84 94.26,70.13 94.26,56.74 94,56.47 94,44.95
  Component Side w10: v1(84,21) 84.06,21.06 C94.2@84.06,35 94,44.95 ; v1@85,699 v1(85,698) 85,681 U2.A2@90.13,675.87 86,680 ; v1(132,693) 132,677 U6.A2@133.13,675.87 ; 351,1060 351.2,1059.8 U7.1@365.63,1059.8 ; C52.2@358,1217.54 358,1195 358,1191 365.63,1183.37 U7.12@365.63,1160.2 ; v1(404,51) 409.37,45.63 U11.A3@421.5,45.63 ; v1(406,95) 416,85 U11.A2@421.5,85
  Component Side w15: v1(197,951.2) 297.2,951.2 330,984 330,1027 ; C77.2@351,1025.99 349.99,1027 330,1027 ; 351.2,1059.8 346.39,1055 330,1055 ; 358,1195 345,1182 v1(330,1182) 330,1055 ; 330,1027 330,1055
  Inner Layer 1 w15: 114,737 102,737 ; v1(132,693) 132,706 139,713 139,723 125,737 102,737 ; v1(197,951.2) 180.81,935 97,935 81,919 81,840 56.5,815.5 56.5,752.5 72,737 102,737
  Inner Layer 2 w10: 19,597 19,584 ; 23.5,251.82 26,249.32 ; v1@45.99,638 v1(48,638) 34,638 19,623 19,584 ; 59.65,215.58 53.62,221.62 ; v1(84,21) v1@87,24 ; 109,72 109,46 ; v1(406,95) 404,93 v1(404,51) 401,48 380,48 364,32 321,32 313,24 v1@87,24 ; 19,584 19,506 30,495 30,477 22,469 22,356 28.02,349.98 28.02,299 23,293.98 23,252.23 53.62,221.62 ; 53.62,221.62 85.69,189.55 85.69,134.32 109,111 109,46 ; v1@87,24 109,46
  Solder Side w8: v1(330,1182) 330,1198 335,1203 R3.2@335,1213.94
  Solder Side w10: 43,649 43,643 ; v1(48,638) 43,643 ; v1(85,698) 79,698 72,705 C32.2@54.06,705 54.06,694.06 43.54,683.54 43.54,643.54 43,643 ; C39.2@130,677.06 v1@130,691 ; v1(132,693) v1@132,696.63
  Solder Side w15: C32.2@54.06,705 54.06,709.06 71.79,726.79 95.56,726.79 105.28,736.5 123.99,736.5 ; 128.25,732.25 123.99,736.5 ; v1(132,693) 132,705 135,708 135,725.49 123.99,736.5
V28P0: C8.2 C10.2 C11.2 C31.2 C49.2 C53.2 D1.2 Q1.2 Q1.3 Q1.6 Q4.2 Q4.3 Q4.6 Q5.2 Q5.3 Q5.6 Q6.2 Q6.3 Q6.6 R11.1 R13.1 R16.1 R17.1 R44.1 | length 1278.7
  Component Side w10: R11.1@342.32,1343 342.32,1358.65 353.67,1370 v1(363,1370) ; v1(451,1213) 451.69,1213.68 R17.1@451.69,1238 ; R13.1@504.94,705 504.94,712.32 508,715.37 v1(508,722) ; v1(598,1325) 598,1331 609.69,1342.68 R44.1@620,1342.68 ; C10.2@613.99,704 621.99,696 v1(636,696) ; R16.1@628.69,1486 628.69,1508.68 v1(635,1515)
  Component Side w15: v1@518,1119.97 518,1094.4 C31.2@526,1086.4 C31.2@538,1098.4 ; v1@538,1119.97 C31.2@538,1098.4 ; v1(558,1121) 558,1118.4 C31.2@538,1098.4 ; v1(582,830) 582,845.6 C49.2@606,869.6 606,840 v1(599,833) ; v1(583,1121) 583,1106.4 C53.2@603,1086.4 ; v1@597,816 v1(593,816) 619.22,816 D1.2@623,819.78 ; v1(602,1121) 603,1120 C53.2@603,1086.4 ; v1(623,1120) 623,1106.4 C53.2@603,1086.4 ; v1(631,1142) 614.4,1142 C8.2@594.4,1162 ; v1(631,1182) 605,1182 594.4,1171.4 C8.2@594.4,1162 ; v1(632,1162) C8.2@594.4,1162 ; v1(632,1212) 614,1212 594.4,1231.6 C11.2@594.4,1233 ; v1(632,1254) 615.4,1254 C11.2@594.4,1233 ; v1(633,1233) C11.2@594.4,1233
  Inner Layer 1 w10: v1(508,722) 508,712 515,705 615,705 ; 623,697 615,705 ; v1(636,696) 624,696 615,705
  Solder Side w10: Q1.2@343.32,1335.16 Q1.3@363,1335.16 363,1337 Q1.6@363,1354.84 363,1364 v1(363,1370) ; Q6.2@410.32,1240.16 Q6.3@430,1240.16 ; Q6.6@430,1259.84 Q6.3@430,1240.16 ; v1(432,1214) 430,1216 Q6.3@430,1240.16 ; v2(576,1433) 591.32,1448.32 Q5.2@591.32,1477.16 602,1477.16 Q5.3@611,1477.16 Q5.6@611,1496.84 611,1505.67 620,1514.67 634.67,1514.67 v1(635,1515) ; v1(598,1325) 603,1330 Q4.6@610.16,1330 Q4.3@629.84,1330 Q4.2@629.84,1310.32 629.84,1283.16 630,1283 630,1281 v1(628.98,1280.02) v1@629,1281
  other v1: 518,1121 538,1121
VCONN: C50.2 C81.2 J3.1 R39.1 TVS9.1 U7.5 U7.7 U7.11 U12.A1 | length 1451.3
  Component Side w10: U7.11@381.38,1160.2 381,1160.57 381,1185.05 392.95,1197 422.63,1197 444.37,1175.26 U7.7@444.37,1160.2 ; C50.2@427.31,1017 C50.2@428.62,1018.31 ; U7.5@428.62,1059.8 428.62,1045.38 v1(437,1037)
  Component Side w15: v1(437,1037) 427.31,1027.31 C50.2@427.31,1017 427.31,1012.69 v1(453,987) ; v1(540,183) C81.2@540,205.31 555.84,221.16 559.27,221.16 U12.A1@575.16,237.05
  Inner Layer 2 w15: 419,767.5 419,738 ; v1(453,987) 448.5,982.5 448.5,951.5 419,922 419,738 ; v1(540,183) 590,233 590,382 508,464 508,661 481.5,687.5 453.5,687.5 419,722 419,738
  Solder Side w5: TVS9.1@273.86,946.14 J3.1@273.86,1003.7
  Solder Side w10: v1(437,1037) 432.94,1041.06 432.94,1058.01 R39.1@429.94,1061 429.94,1073.94 445,1089 445,1174 v1(437,1182)
WAKE_RX: R7.2 U3.C12 | length 683.1
  Inner Layer 1 w5: 28,616 28,606 ; 30.59,619.06 32,620.47 32,646 ; 31.76,620.24 28,616.47 28,606 ; 32,641.77 32,646 ; 58.46,471.54 52,478 ; 70,693 91,672 ; 74.21,688.79 69,694 62,694 54,694 32,672 32,646 ; 86.37,676.63 92,671 v1(92,639) ; v1(191.89,294.37) 185.7,288.18 158.91,288.18 126.65,320.44 126.65,460.35 121.73,465.27 64.73,465.27 52,478 ; 28,606 28,600 28,594 28,502 52,478
  Solder Side w5: v1(92,639) 98.5,645.5 98.5,651 ; 98.5,647.5 98.5,651 ; R7.2@99,658.94 98.5,658.45 98.5,651
WAKE_RX_PWR: D3.1 R7.1 U2.B2 | length 111.5
  Component Side w8: D3.1@63.98,751.61 92.87,722.72 101,714.59 v1@101,693 ; v1(103,691) v1@101,693 ; U2.B2@105.87,675.87 105.87,688.13 v1@101,693
  Solder Side w8: R7.1@99,677.06 99,683 99,687 v1(103,691)
WAKE_TX: R2.2 R4.2 U3.A11 | length 1613.3
  Inner Layer 1 w5: 19.5,496.36 18,497.86 ; 57,712 38,712 ; 117,687 117,684 ; v1@177.04,653.04 v1(178,653.04) 141.96,653.04 117,678 117,684 ; v1(211.57,255) 205.39,261.18 107.67,261.18 87.2,281.66 87.2,299.88 79.89,307.2 79.89,339.89 88,348 88,379 77,390 50,390 25.43,414.57 25.43,490.43 18,497.86 ; 18,497.86 18,621 22,625 22,696 38,712 ; 38,712 102,712 117,697 117,684
  Inner Layer 2 w5: v1@178.46,653.5 v1(178,653.04) 198.46,673.5 219,673.5 ; 215.5,673.5 219,673.5 ; v1(389,1217) 384.5,1212.5 384.5,1144.5 413.15,1115.85 413.15,1048 ; 413.15,1035.85 413.15,1048 ; 219,673.5 224.59,673.5 232.5,681.41 232.5,697.27 219.5,710.27 219.5,846.64 265.86,893 335,893 413.15,971.15 413.15,1048
  Solder Side w5: v1(178,653.04) 180.96,656 R2.2@186.94,656 ; R4.2@371,1213.94 382.94,1213.94 386,1217 v1(389,1217)
pads on no net: U3.A3 U3.A4 U3.A5 U3.A6 U3.A7 U3.A8 U3.A9 U3.A12 U3.A13 U3.A14 U3.A15 U3.A16 U3.A17 U3.B3 U3.B4 U3.B5 U3.B6 U3.B7 U3.B8 U3.B9 U3.B10 U3.B11 U3.B12 U3.B14 U3.B15 U3.B16 U3.B17 U3.C2 U3.C6 U3.C7 U3.C8 U3.C9 U3.C10 U3.C11 U3.C14 U3.D1 U3.D2 U3.D18 U3.E1 U3.E2 U3.E17 U3.E18 U3.F1 U3.F3 U3.F17 U3.F19 U3.G1 U3.G2 U3.G3 U3.G17 U3.H3 U3.H7 U3.H14 U3.H17 U3.H18 U3.H19 U3.J2 U3.J17 U3.J18 U3.K2 U3.K18 U3.L1 U3.L2 U3.L3 U3.L6 U3.L14 U3.L18 U3.L19 U3.M1 U3.M2 U3.M3 U3.M7 U3.M13 U3.M17 U3.M18 U3.M19 U3.N2 U3.N3 U3.N17 U3.N19 U3.P3 U3.P6 U3.R1 U3.R2 U3.R3 U3.T1 U3.T2 U3.T3 U3.T10 U3.T19 U3.U1 U3.U2 U3.U10 U3.U18 U3.U19 U3.V1 U3.V2 U3.V6 U3.V7 U3.V8 U3.V9 U3.V12 U3.V13 U3.V14 U3.V15 U3.W2 U3.W5 U3.W6 U3.W8 U3.W9 U3.W11 U3.W12 U3.W14 U3.W15 U4.2 U4.5 U7.8
copper on no net: | length 90
  Solder Side w12: v1(481,891) 498,874 564,874

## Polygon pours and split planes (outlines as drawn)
V1P2 on Component Side "TopLayer-No Net" (solid, remove dead copper, pour order 17): 514,424 560,424 562,422 562,385 562,367 558,363 544,349 509,349 496,349 489,356 488,357 488,369 488,370 490,372 492,374 504,374 505,374 510,379 510,408 510,420 514,424
GND on Component Side "TopLayer-No Net" (solid, remove dead copper, pour order 16): 587,445 624,445 631,438 631,401 631,368 624,361 612,349 612,302 612,284 607,279 559,279 557,279 555,281 554,282 554,344 568,358 575,365 575,376 575,438 579,442 582,445 587,445
V3P3 on Component Side "TopLayer-No Net" (solid, remove dead copper, pour order 15): 475,342 507,342 531,342 535,338 535,297 535,283 532,280 531,279 469,279 451,279 443,287 441,289 441,305 441,321 448,328 462,342 475,342
V1P2 on Component Side "Mechanical 1-No Net" (solid, pour order 14): 415,116 415,104 419,100 420,99 439,99 444,94 444,84 444,78 449,73 481,73 485,77 485,138 481,142 478,145 422,145 418,145 415,142 415,116
GND on Component Side "Mechanical 1-No Net" (solid, pour order 13): 105,68 109,72 155,72 166,72 171,67 171,28 166,23 106,23 104,25 104,67 105,68
GND on Component Side "Mechanical 1-No Net" (solid, pour order 12): 336,31 365,31 372,38 372,111 372,149 380,157 402,157 407,157 410,154 472,154 477,159 481,163 481,183 476,188 456,188 442,188 434,180 433,179 412,179 356,179 350,173 334,157 334,112 334,33 336,31
V3P3 on Component Side "Top Solder-No Net" (solid, remove dead copper, pour order 11): 68,76 66,74 23,74 23,148 26,151 169,151 175,145 175,93 167,85 110,85 102,93 99,96 81,96 73,96 68,91
V1P2 on Inner Layer 2 "TopLayer-No Net" (solid, remove dead copper, pour order 18): 393,525 525.09,392.91 525.09,99.21 517.6,91.72 416.28,91.72 308,200 261,200 120,341 120,489 156,525
VCONN on Inner Layer 1 "Inner Layer 1-No Net" (solid, pour order 10): 230,963 230,1026 251,1047 372,1047 400,1075 456,1075 494,1037 494,945 492,945 474,927 445,898 399,898 388,898 350,936 344,942 264,942 251,942 230,963
GND on Ground Plane (GND) (split plane): 556.42,18.15 556.27,17.8 556.42,18.15
GND on Ground Plane (GND) (split plane): 987.35,16.96 987.34,16.96 987.34,17.02
GND on Ground Plane (GND) (split plane): 19.68,1607.1 95.29,1607.1 95.29,1448.03 95.3,1447.96 95.62,1443.85 96.6,1439.76 98.21,1435.89 100.4,1432.31 103.13,1429.11 106.32,1426.39 109.9,1424.19 113.78,1422.59 117.86,1421.61 121.98,1421.28 122.05,1421.27 538.74,1421.27 538.77,1421.28 543.01,1421.61 547.18,1422.61 551.14,1424.26 554.8,1426.5 558.06,1429.28 560.85,1432.54 563.09,1436.2 564.73,1440.16 565.73,1444.33 566.07,1448.57 566.07,1448.61 566.07,1607.1 652.38,1607.1 652.38,1566.93 652.39,1566.86 652.71,1562.74 653.69,1558.66 655.3,1554.78 657.49,1551.2 660.22,1548.01 663.41,1545.29 666.99,1543.09 670.87,1541.49 674.95,1540.51 679.06,1540.18 679.13,1540.17 1531.76,1540.17 1532.04,1540.21 1534.92,1539.92 1537.97,1539 1540.78,1537.5 1543.24,1535.48 1545.26,1533.02 1546.76,1530.21 1547.68,1527.17 1547.97,1524.28 1547.93,1524 1547.93,20 1547.96,19.79 1547.73,17.47 1546.99,15.03 1545.79,12.79 1544.18,10.82 1542.21,9.21 1539.97,8.01 1537.53,7.27 1535.21,7.04 1535,7.07 987.39,7.07 987.39,16.48 987.34,16.87 987.35,16.96 987.94,16.96 987.47,18.12 987.26,18.09 987.01,21.2 986.02,25.33 984.39,29.25 982.17,32.87 979.42,36.1 976.19,38.86 972.56,41.08 968.64,42.71 964.51,43.7 961.4,43.94 961.43,44.15 960.28,44.63 960.28,44.03 960.33,44.03 960.28,44.03 960.18,44.02 959.8,44.07 584.81,44.07 583.37,43.88 582.2,43.73 581.85,43.58 582.2,43.73 583.37,43.88 583.37,44.3 581.58,43.56 579.13,43.37 575,42.38 571.08,40.75 567.46,38.53 564.23,35.77 561.47,32.54 559.25,28.92 557.62,25 556.63,20.87 556.44,18.42 555.7,16.63 556.12,16.63 555.93,15.19 555.93,7.07 68.19,7.07 68.21,7.17 67,7.67 67,7.07 66.91,7.06 66.5,7.11 66.09,7.06 66,7.07 66,7.67 64.79,7.17 64.81,7.07 19,7.07 18.81,7.05 16.66,7.26 14.42,7.94 12.35,9.05 10.53,10.53 9.05,12.35 7.94,14.42 7.26,16.66 7.05,18.81 7.07,19 7.07,1594.49 7.04,1594.69 7.27,1596.96 7.99,1599.33 9.16,1601.52 10.73,1603.44 12.65,1605.02 14.84,1606.19 17.21,1606.91 19.48,1607.13
no net on Power Plane (VCC) (split plane): 556.42,18.15 556.27,17.8 556.42,18.15
no net on Power Plane (VCC) (split plane): 987.35,16.96 987.34,16.96 987.34,17.02
V3P3 on Power Plane (VCC) (split plane): 231 vertices, not listed, extent 7.04,7.04 1547.97,1607.13

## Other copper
Component Side:
  text "Top" at 177.17,-433.07 h60
Inner Layer 1:
  text "SIG1_LAYER3" at 0,-413.39 h60
Inner Layer 2:
  text "SIG2_LAYER4" at -39.37,-393.7 h60
Solder Side:
  text "Bottom" at 137.8,-452.76 h60
Ground Plane (GND) (plane layer: these items are gaps in the copper):
  text "GND_LAYER2" at -39.37,-374.02 h60
Power Plane (VCC) (plane layer: these items are gaps in the copper):
  lines w20: 324,1346 324,1428.35 ; 325,1355 325,1345 390,1280 390,1180 435,1135 435,1055 510,980 510,795 510,785 ; 484,760 484,746 555,675 648.45,675 658.45,665 ; 485,750 485,760 510,785 ; 495,770 510,785
  text "PWR_LAYER5" at -19.68,-433.07 h60

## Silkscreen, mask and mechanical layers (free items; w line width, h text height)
Top Overlay:
  text "K" at 599,819 h8
  text "A" at 595,786 h14
  text "K" at 34,769 h8
  text "K" at 597,756 h8
  text "A" at 76,734 h14
  text "A" at 595,722 h14
  text "A" at 78,708 h14
  text "K" at 15,679 h8
  text "Top Overlay" at -19.68,-433.07 h14
Bottom Overlay:
  text "+" at 414,985 h30 r90
  text "-" at 414,889.5 h30 r90
  text "T" at 414,794 h30 r90
  text "Bottom Overlay" at -118.11,-433.07 h60
Top Paste:
  text "Top Paste" at -39.37,-413.39 h60
Bottom Paste:
  text "Bottom Paste" at -59.06,-433.07 h60
Top Solder:
  text "Top Solder" at 0,-374.02 h60
Bottom Solder:
  text "Bottom Solder" at -59.06,-452.76 h60
DIMENSION:
  lines w1: -0.01,19.69 ccw(c19.68,19.69) 19.68,0.01 ; 102.35,1450.4 ccw(c122.04,1450.4) 122.04,1430.72 ; 489.36,1430.72 ccw(c489.36,1450.4) 509.05,1450.4 ; 512.98,17.72 cw(c532.67,17.72) 532.67,37.41
OUTLINE:
  lines w6: 66,0 19,0 cw(c19,19) 0,19 0,1594.49 cw(c19.68,1594.49) 19.68,1614.17 102.36,1614.17 102.36,1448.03 ccw(c122.05,1448.03) 122.05,1428.35 538.74,1428.35 ccw(c538.74,1448.61) 559,1448.61 559,1614.12 ; 67,0 562.99,0 563,16.63 ; 559.05,1614.17 659.45,1614.17 659.45,1566.93 ccw(c679.13,1566.93) 679.13,1547.24 1531.76,1547.24 cw(c1531.76,1524) 1555,1524 1555,20 cw(c1535,20) 1535,0 980.31,0 980.31,16.96 ccw(c960.28,16.96) 960.28,36.96 ; 563.37,16.63 cw(c583.37,16.63) 583.37,36.63 ; 583.37,37 960.28,37
Mechanical 4:
  region: 615.16,1603.35 574.8,1603.35 574.8,1613.19 615.16,1613.19
  region: 59.06,1603.35 18.7,1603.35 18.7,1613.19 59.06,1613.19
  region: 0.98,39.37 0.98,157.48 10.83,157.48 10.83,39.37
  region: 0.98,196.85 0.98,314.96 10.83,314.96 10.83,196.85
  region: 0.98,354.33 0.98,472.44 10.83,472.44 10.83,354.33
  region: 0.98,511.81 0.98,629.92 10.83,629.92 10.83,511.81
  region: 0.98,669.29 0.98,787.4 10.83,787.4 10.83,669.29
  region: 0.98,826.77 0.98,944.88 10.83,944.88 10.83,826.77
  region: 0.98,984.25 0.98,1102.36 10.83,1102.36 10.83,984.25
  region: 0.98,1141.73 0.98,1259.84 10.83,1259.84 10.83,1141.73
  region: 0.98,1299.21 0.98,1417.32 10.83,1417.32 10.83,1299.21
  region: 0.98,1456.69 0.98,1574.8 10.83,1574.8 10.83,1456.69
  region: 354.33,10.83 472.44,10.83 472.44,0.98 354.33,0.98
  region: 196.85,10.83 314.96,10.83 314.96,0.98 196.85,0.98
  region: 39.37,10.83 157.48,10.83 157.48,0.98 39.37,0.98
ASSY_TOP:
  text "ASSY TOP" at 11,-291 h60
ASSY_BOT:
  text "ASSY BOTTOM" at 611,-291 h60
Drill Drawing:
  lines w1: -87.31,0.01 -0.01,0.01 -0.01,-91.17 ; 102.35,1614.18 102.35,1658.11 ; 559.05,1613.18 559.05,1653.17 ; 562.99,-43.92 562.99,0.01 ; 593.06,1614.17 708.66,1614.17 ; 609.44,37.41 658.9,37.41 ; 609.44,1614.18 634.78,1614.18 ; 650.69,37.4 737.99,37.4 ; -185.05,1712.61 -296.71,1712.61 -185.05,1712.61 ; -185.05,1712.61 2.41,1603.94 ; -185.05,1712.61 2.41,1603.94 ; -146.18,1661.63 -121.5,1704.21 ; -146.18,1661.63 2.41,1603.94 ; -146.18,1661.63 -121.5,1704.21 ; -146.18,1661.63 2.41,1603.94 ; -121.5,1704.21 2.41,1603.94 ; -121.5,1704.21 2.41,1603.94
  lines w6: -1014.47,2168.38 -1014.47,2921.66 cw(c-974.8,2921.66) -974.8,2961.33 1621.53,2961.33 cw(c1621.53,2927.33) 1655.53,2927.33 ; -1014.47,2170.33 ccw(c-980.47,2170.33) -980.47,2136.33 ; -984,2136.33 1611,2135.65 ; -955.69,2768.65 1594.31,2768.65 ; -951,2868 1599,2868 ; 1609.01,2135.65 ccw(c1609.01,2181.89) 1655.25,2181.89 ; 1655.53,2181.89 1655.53,2926.33
  text "6 Layers Stack Up" at -210,2893 h57
  text "FAB NOTES:" at 4947.32,2890.98 h60
  text "Layer" at -951,2828 h24
  text "Gerber" at -51,2828 h24
  text "Copper" at 609,2828 h24
  text "Dielectric" at 1109,2828 h24
  text "Name" at -951,2788 h24
  text "Document" at -51,2788 h24
  text "Thickness" at 609,2788 h24
  text "Material" at 1109,2788 h24
  text "1. Materials: Green clad, FR-4/Epoxy class,or equivalent.dielectric costant 4.2+/-0.2 ," at 5055,2745 h60
  text "Top Solder Mask" at -951,2708 h34
  text "(.GTS)" at -51,2708 h34
  text "0.5mil" at 749,2708 h34
  text "Solder Resist" at 1109,2708 h34
  text "Top" at -951,2628 h34
  text "(.GTL)" at -51,2628 h34
  text "1.58mil" at 469,2628 h34
  text "see cross section for board thickness, copper" at 5215,2625 h60
  text "3.5mil" at 749,2588 h34
  text "FR4" at 1109,2588 h34
  text "GND_IN2" at -951,2548 h34
  text "(.GP1)" at -51,2548 h34
  text "0.65mil" at 469,2548 h34
  text "2.5mil" at 749,2508 h34
  text "FR4" at 1109,2508 h34
  text "weight and layer structures." at 5215,2505 h60
  text "SIG1_IN3" at -951,2468 h34
  text "(.G1)" at -51,2468 h34
  text "0.65mil" at 469,2468 h34
  text "2.5mil" at 749,2428 h34
  text "FR4" at 1109,2428 h34
  text "SIG2_IN4" at -951,2388 h34
  text "(.G2)" at -51,2388 h34
  text "0.65mil" at 469,2388 h34
  text "2. Components on the top and bottom layers." at 5035,2385 h60
  text "2.5mil" at 749,2348 h34
  text "FR4" at 1109,2348 h34
  text "PWR_IN5" at -951,2308 h34
  text "(.GP2)" at -51,2308 h34
  text "0.65mil" at 469,2308 h34
  text "3.5mil" at 749,2268 h34
  text "FR4" at 1109,2268 h34
  text "3. Minimum signal trace width/spacing : 4/5 mils." at 5035,2265 h60
  text "Bottom" at -951,2228 h34
  text "(.GBL)" at -51,2228 h34
  text "1.58mil" at 469,2228 h34
  text "Bottom Solder Mask" at -951,2148 h34
  text "(.GBS)" at -51,2148 h34
  text "0.5mil" at 749,2148 h34
  text "Solder Resist" at 1109,2148 h34
  text "4. Drilling:" at 5035,2145 h60
  text "4.1  minimum hole size is 6 mils drill." at 5195,2025 h60
  text "Overall Thickness :21.26 mil+/-10%" at -435,2011 h50
  text "4.2  all plated holes are to be plated thru and with min .001 thick." at 5195,1905 h60
  text "4.3  all hole diameters are finished sizes." at 5195,1785 h60
  text "R0.5" at -429.14,1692.92 h31
  text "5X" at -500.01,1688.98 h31
  text "2.6" at 106.29,1681.11 h31 r90
  text "14.2" at 565.74,1680.11 h31 r90
  text "4.4  all holes to be +/-0.003 from true position unless" at 5195,1665 h60
  text "41" at 727,1599 h31
  text "otherwise specified for PTH, or +/-0.002 if it's NPTH." at 5415,1565 h60
  text "4.5  NC drill file has been supplied, see hole size table." at 5195,1445 h60
  text "5. Front to back pattern shall register within .005\"." at 5035,1325 h60
  text "6. Layer to layer(pattern to pattern) registration to be +/-.005\"." at 5035,1205 h60
  text "7. Soldermask: Both sides of board, Liquid Photo Imageable, soldermask" at 5035,1085 h60
  text "over bare copper (SMOBC), green." at 5206,960 h60
  text "8. Warpage and twist to meet IPC class II." at 5035,845 h60
  text "9. Silkscreen using white non-conductive epoxy or eqv." at 5035,725 h60
  text "10. Finish:" at 4995,585 h60
  text "10.1  Edge to be free of loose sliver and rough edge." at 5195,465 h60
  text "10.2  Finished board shall not have nicks scratches, voids," at 5195,345 h60
  text "exposed copper, poor plating or misdrilled holes." at 5526,240 h60
  text "10.3  Trace width tol=+/-.001\" of finished trace width." at 5195,125 h60
  text "11. Date code and UL rating shall be permanently marked or etched on PCB." at 4995,5 h60
  text "0" at -133.56,-15.49 h31
  text "12. Remove non-functional pad on all inner layers and planes" at 4995,-115 h60
  text "unit:mm" at 87.8,-119.61 h63
  text "0" at -11.51,-145.41 h31
  text "14.3" at 580,-145 h31 r90
  text "13. Impedance control:" at 4996,-260 h60
  text "13.1 Differential pairs:" at 5206,-400 h60
  text "FAB DRAWING" at -39.37,-452.76 h75
  text "4/8 mils width/gap on top and bottom layers should be controlled 100 ohms +/- 10% ." at 5225,-545 h60
  text "13.2 Single ended signals:" at 5226,-695 h60
  text "5 mils width on top layer should be controlled 50 ohms +/-10% ." at 5304,-842 h60
  text "14. This board use Via-in-Pad design for U3 component." at 4994,-975 h60
  text ".Legend" at -82,-1702 h60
